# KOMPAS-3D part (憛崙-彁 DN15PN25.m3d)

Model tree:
1. Объединить компоненты:1  (labels: СЕНС-ПР DN15PN25)

Referenced files in D:\Савин\!СЕНСОР\3D для заказчика\!Новый перечень\СЕНС-ПР\1. СЕНС-ПР\DN15\: СЕНС-ПР DN15PN25.a3d
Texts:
  СЕНС-ПР DN15PN25
  ООО НПП Сенсор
